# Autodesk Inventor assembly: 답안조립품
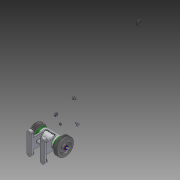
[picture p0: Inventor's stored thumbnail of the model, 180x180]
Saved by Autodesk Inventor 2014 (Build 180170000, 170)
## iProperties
Created: 2015-11
Part Number: 답안조립품
Document SubType Name: Assembly
Designer: test_25
Author: test_25
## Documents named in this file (16)
- C:\Users\test_25\Desktop\451109V1041\답안조립품.iam
- C:\Users\test_25\Desktop\451109V1041\1-본체.ipt
- C:\Users\test_25\Desktop\451109V1041\V벨트풀리.ipt
- C:\Users\test_25\Desktop\451109V1041\너트 M 8.ipt
- C:\Users\test_25\Desktop\451109V1041\니플 M 6 x 0.75.ipt
- C:\Users\test_25\Desktop\451109V1041\베어링 15 x 32 x 9.ipt
- C:\Users\test_25\Desktop\451109V1041\볼트 M 6 x 8.ipt
- C:\Users\test_25\Desktop\451109V1041\볼트 M4 x 12.ipt
- C:\Users\test_25\Desktop\451109V1041\스퍼기어.ipt
- C:\Users\test_25\Desktop\451109V1041\스프링와셔 8.ipt
- C:\Users\test_25\Desktop\451109V1041\오일 실 15 25 7.ipt
- C:\Users\test_25\Desktop\451109V1041\와셔 6x11.5.ipt
- C:\Users\test_25\Desktop\451109V1041\와셔 8x17.ipt
- C:\Users\test_25\Desktop\451109V1041\축.ipt
- C:\Users\test_25\Desktop\451109V1041\커버.ipt
- C:\Users\test_25\Desktop\451109V1041\키 3 x 3 x 12.ipt
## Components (8 placed, 4 different names)
1. 1-본체:1
2. V벨트풀리:1
3. KS B 2023 6002 - 15 x 32 x 9:1
4. KS B 2023 6002 - 15 x 32 x 9:2
5. ISO 4762 M4 x 12:1
6. ISO 4762 M4 x 12:2
7. ISO 4762 M4 x 12:3
8. ISO 4762 M4 x 12:4
